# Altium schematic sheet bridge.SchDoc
size 431 x 279 mm; Date: Not shown in title block; ApprovedBy: Not shown in title block; CheckedBy: Not shown in title block; Author: Not shown in title block; CompanyName: Not shown in title block; Engineer: Not shown in title block; Organization: Not shown in title block; Address1: Not shown in title block; Address2: Not shown in title block; Address3: Not shown in title block; Address4: Not shown in title block; DocumentNumber: 3; Revision: Use project parameter SCH_Rev; SheetNumber: 3; SheetTotal: 6; PageSetup: Record=PageOptions¦CenterHorizontal=True¦CenterVertical=True¦PrintScale=1.00¦XCorrection=1.00¦YCorrection=1.00¦PrintKind=0¦BorderSize=5000000¦LeftOffset=0¦BottomOffset=0¦Orientation=2¦PaperLength=1000¦PaperWidth=1000¦Scale=100¦PaperSource=15¦PrintQuality=600¦MediaType=1¦DitherType=10¦PaperKind=Letter¦PrintScaleMode=1
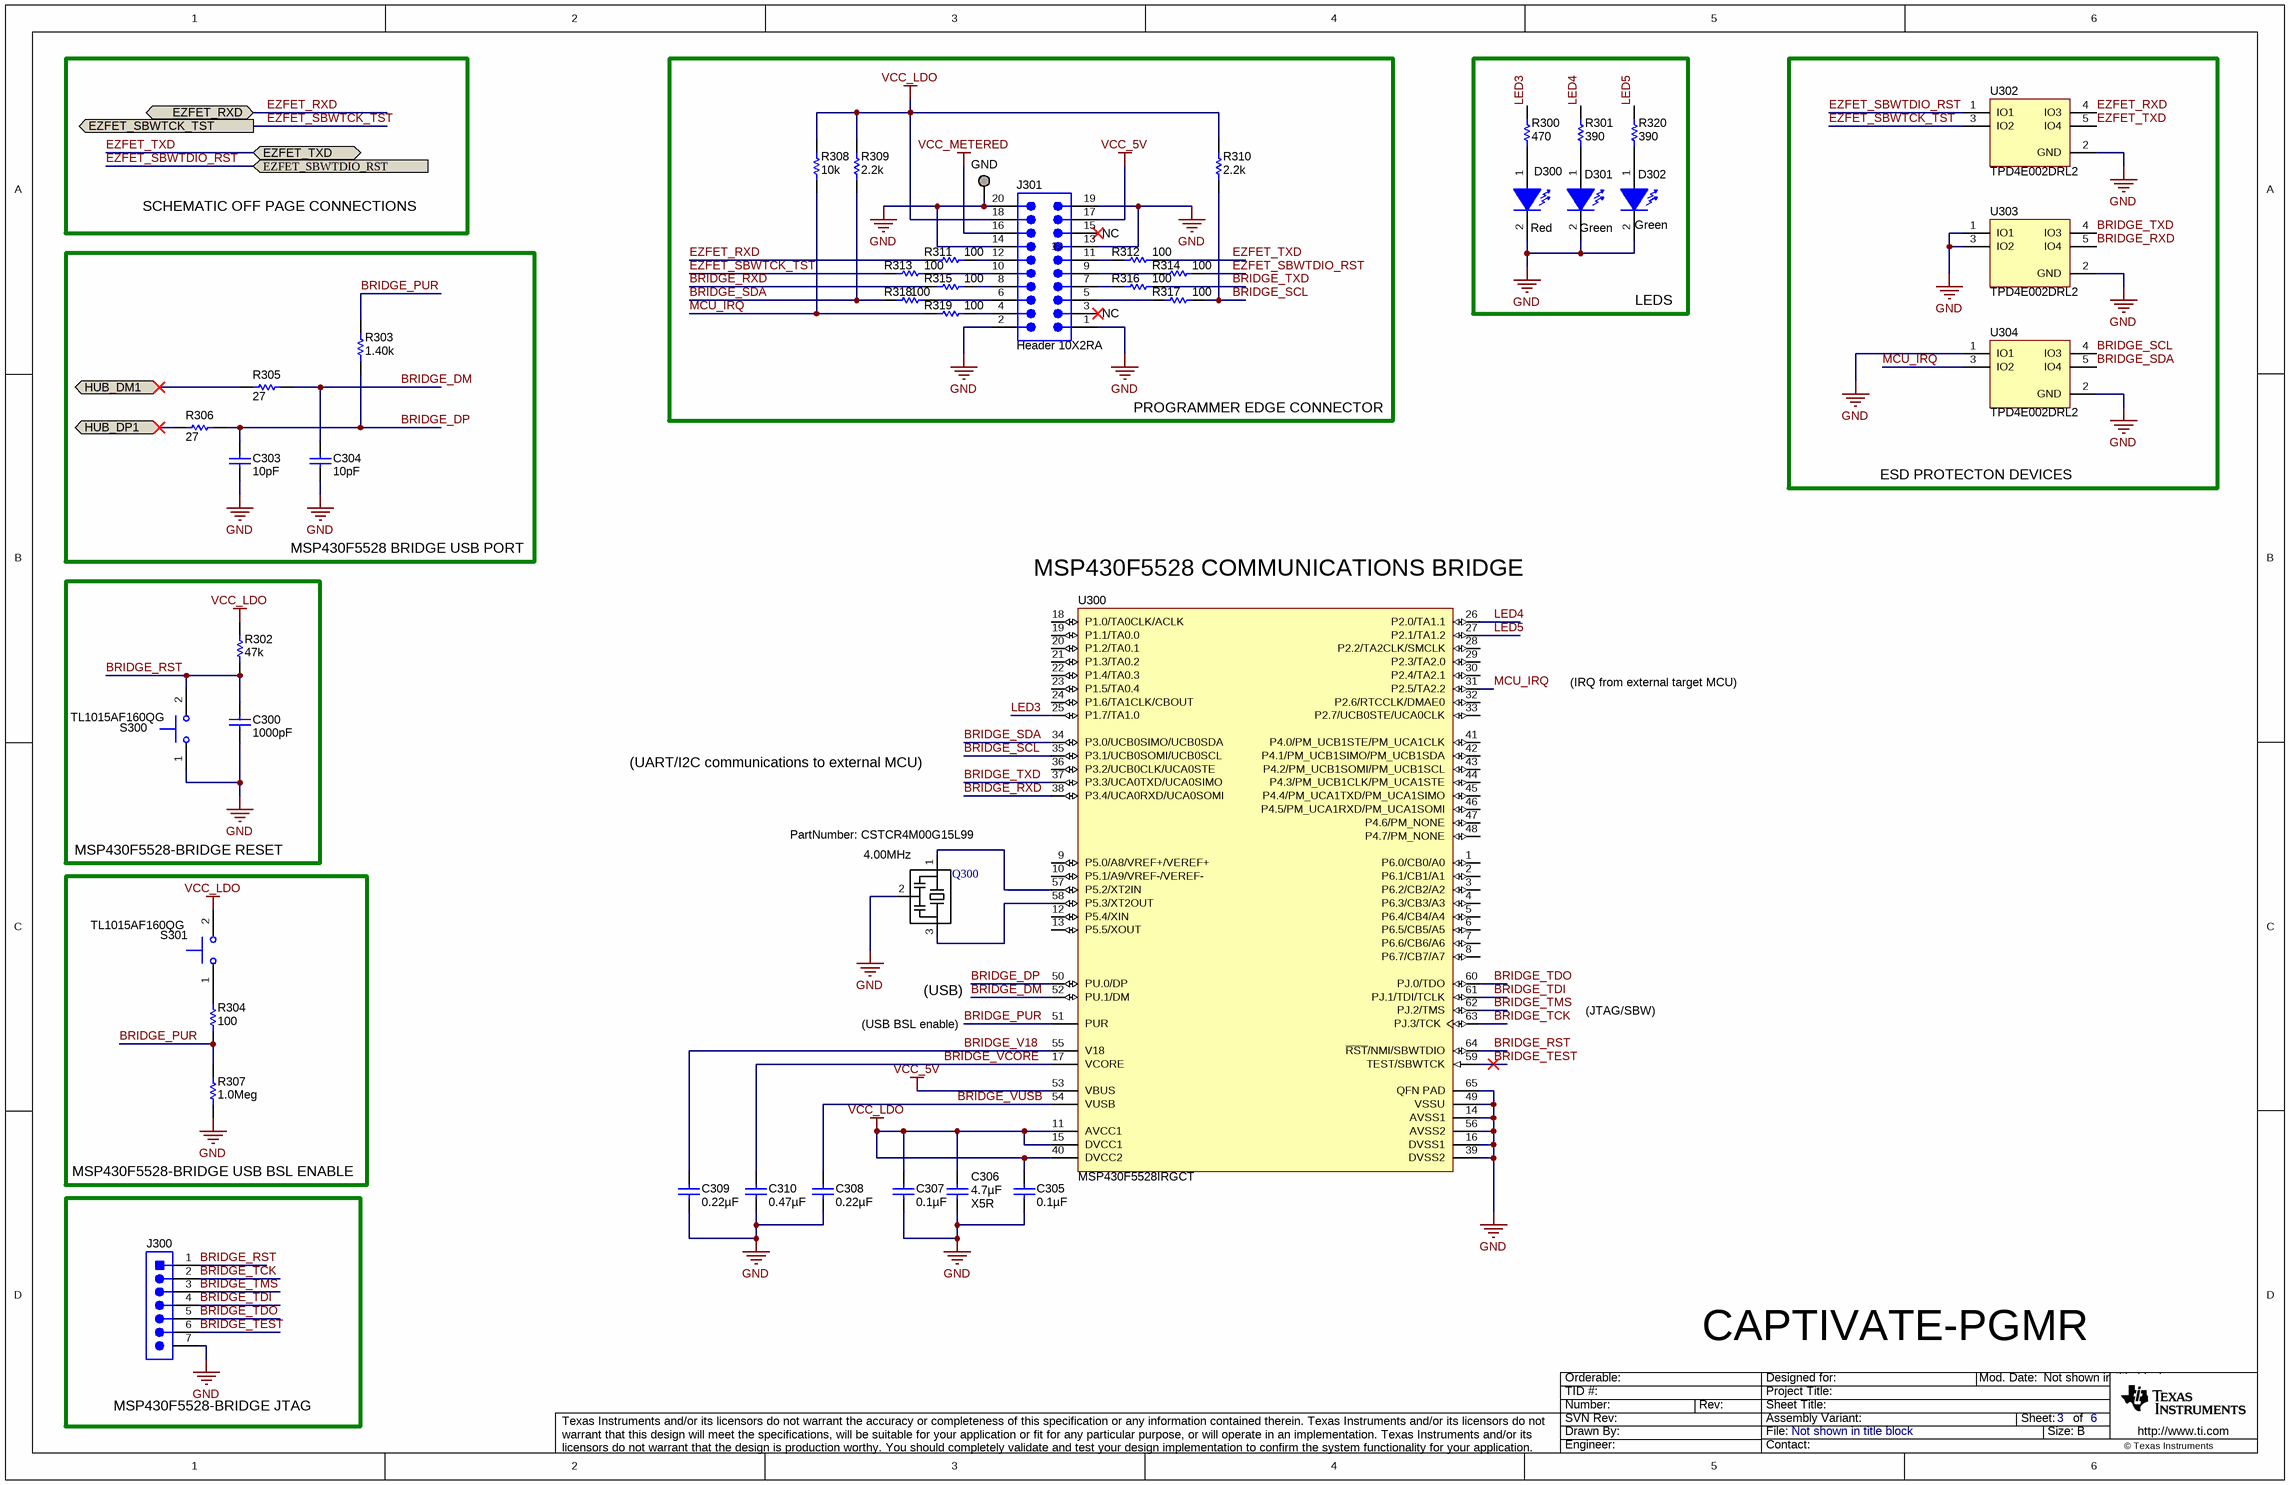
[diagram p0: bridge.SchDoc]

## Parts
C300  ValueDisplayed: 1000pF  [0402]  (hidden comment: C1005X7R1H102K)
C303  ValueDisplayed: 10pF  [0402]  (hidden comment: GRM1555C1H100JA01D)
C304  ValueDisplayed: 10pF  [0402]  (hidden comment: GRM1555C1H100JA01D)
C305  ValueDisplayed: 0.1µF  [0402]  (hidden comment: GRM155R61C104KA88D)
C306  ValueDisplayed: 4.7µF  TempCo: X5R  [0603]  (hidden comment: CGB3B1X5R1A475K055AC)
C307  ValueDisplayed: 0.1µF  [0402]  (hidden comment: GRM155R61C104KA88D)
C308  ValueDisplayed: 0.22µF  [0402]  (hidden comment: GRM155R61A224KE19D)
C309  ValueDisplayed: 0.22µF  [0402]  (hidden comment: GRM155R61A224KE19D)
C310  ValueDisplayed: 0.47µF  [0402]  (hidden comment: GRM155R61A474KE15D)
D300  value Red  [LED_LTST-C190_Red]  (hidden comment: LTST-C190CKT)
D301  value Green  [LED_LTST-C190]  (hidden comment: LTST-C190GKT)
D302  value Green  [LED_LTST-C190]  (hidden comment: LTST-C190GKT)
GND  TESTPOINT  [TP_VIA_060RND040]  (value not drawn)  (no BOM)
J300  GRPB071VWVN-RC  [Sullins_GRPB071VWVN-RC]  (value not drawn)
J301  Header 10X2RA  [HDR2X10RA]
Q300  Value Displayed: 4.00MHz  PartNumber: CSTCR4M00G15L99  [CSTCR CERAMIC RESONATOR - MURATA]  (hidden comment: RATA-FILTER_CSTCR4M00G15)
R300  value 470  [0402]  (hidden comment: CRCW0402470RJNED)
R301  value 390  [0402]  (hidden comment: CRCW0402390RJNED)
R302  value 47k  [0402]  (hidden comment: CRCW040247K0JNED)
R303  value 1.40k  [0402]  (hidden comment: CRCW04021K40FKED)
R304  value 100  [0402]  (hidden comment: CRCW0402100RJNED)
R305  value 27  [0402]  (hidden comment: CRCW040227R0JNED)
R306  value 27  [0402]  (hidden comment: CRCW040227R0JNED)
R307  value 1.0Meg  [0402]  (hidden comment: CRCW04021M00JNED)
R308  ValueDisplayed: 10k  [0402]  (hidden comment: CRCW040210K0JNED)
R309  ValueDisplayed: 2.2k  [0402]  (hidden comment: CRCW04022K20JNED)
R310  ValueDisplayed: 2.2k  [0402]  (hidden comment: CRCW04022K20JNED)
R311  ValueDisplayed: 100  [0402]  (hidden comment: CRCW0402100RJNED)
R312  ValueDisplayed: 100  [0402]  (hidden comment: CRCW0402100RJNED)
R313  ValueDisplayed: 100  [0402]  (hidden comment: CRCW0402100RJNED)
R314  ValueDisplayed: 100  [0402]  (hidden comment: CRCW0402100RJNED)
R315  ValueDisplayed: 100  [0402]  (hidden comment: CRCW0402100RJNED)
R316  ValueDisplayed: 100  [0402]  (hidden comment: CRCW0402100RJNED)
R317  ValueDisplayed: 100  [0402]  (hidden comment: CRCW0402100RJNED)
R318  ValueDisplayed: 100  [0402]  (hidden comment: CRCW0402100RJNED)
R319  ValueDisplayed: 100  [0402]  (hidden comment: CRCW0402100RJNED)
R320  value 390  [0402]  (hidden comment: CRCW0402390RJNED)
S300  TL1015AF160QG  [SW_TL1015AF160QG]
S301  TL1015AF160QG  [SW_TL1015AF160QG]
U300  MSP430F5528IRGCT  [RGC0064B]
U302  TPD4E002DRL2  [DRL0005A]
U303  TPD4E002DRL2  [DRL0005A]
U304  TPD4E002DRL2  [DRL0005A]

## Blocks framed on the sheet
PROGRAMMER EDGE CONNECTOR: GND J301 R308-R319
LEDS: D300-D302 R300 R301 R320
ESD PROTECTON DEVICES: U302-U304
MSP430F5528 BRIDGE USB PORT: C303 C304 R303 R305 R306
MSP430F5528-BRIDGE RESET: C300 R302 S300
MSP430F5528-BRIDGE USB BSL ENABLE: R304 R307 S301
MSP430F5528-BRIDGE JTAG: J300

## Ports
EZFET_RXD (bidir), EZFET_SBWTCK_TST, EZFET_SBWTDIO_RST, EZFET_TXD (bidir), HUB_DM1 (bidir), HUB_DP1 (bidir)

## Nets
GND: C300.2 C303.2 C304.2 C305.2 C306.2 C307.2 C308.2 C309.2 C310.2 D300.2(K) D301.2(K) D302.2(K) GND.1 J300.7 J301.1 J301.2 J301.13 J301.14 J301.19 J301.20 Q300.2 R307.1 S300.1 U300.14(AVSS1) U300.16(DVSS1) U300.39(DVSS2) U300.49(VSSU) U300.56(AVSS2) U300.65(QFN_PAD) U302.2(GND) U303.1(IO1) U303.2(GND) U303.3(IO2) U304.1(IO1) U304.2(GND)
VCC_5V: J301.17 U300.53(VBUS)
VCC_LDO: C305.1 C306.1 C307.1 J301.18 R302.2 R308.2 R309.2 R310.1 S301.2 U300.11(AVCC1) U300.15(DVCC1) U300.40(DVCC2)
VCC_METERED: J301.16
BRIDGE_DM: C304.1 R305.2 U300.52(PU.1/DM)
BRIDGE_DP: C303.1 R303.1 R306.2 U300.50(PU.0/DP)
BRIDGE_PUR: R303.2 R304.1 R307.2 U300.51(PUR)
BRIDGE_RST: C300.1 J300.1 R302.1 S300.2 U300.64(~{RST}/NMI/SBWTDIO)
BRIDGE_RXD: R315.1 U300.38(P3.4/UCA0RXD/UCA0SOMI) U303.5(IO4)
BRIDGE_SCL: R310.2 R317.2 U300.35(P3.1/UCB0SOMI/UCB0SCL) U304.4(IO3)
BRIDGE_SDA: R309.1 R318.1 U300.34(P3.0/UCB0SIMO/UCB0SDA) U304.5(IO4)
BRIDGE_TCK: J300.2 U300.63(PJ.3/TCK)
BRIDGE_TDI: J300.4 U300.61(PJ.1/TDI/TCLK)
BRIDGE_TDO: J300.5 U300.60(PJ.0/TDO)
BRIDGE_TEST: J300.6 U300.59(TEST/SBWTCK)
BRIDGE_TMS: J300.3 U300.62(PJ.2/TMS)
BRIDGE_TXD: R316.2 U300.37(P3.3/UCA0TXD/UCA0SIMO) U303.4(IO3)
BRIDGE_V18: C309.1 U300.55(V18)
BRIDGE_VCORE: C310.1 U300.17(VCORE)
BRIDGE_VUSB: C308.1 U300.54(VUSB)
EZFET_RXD: R311.1 U302.4(IO3) ; port EZFET_RXD
EZFET_SBWTCK_TST: R313.1 U302.3(IO2) ; port EZFET_SBWTCK_TST
EZFET_SBWTDIO_RST: R314.2 U302.1(IO1) ; port EZFET_SBWTDIO_RST
EZFET_TXD: R312.2 U302.5(IO4) ; port EZFET_TXD
HUB_DM1: R305.1 ; port HUB_DM1
HUB_DP1: R306.1 ; port HUB_DP1
LED3: R300.2 U300.25(P1.7/TA1.0)
LED4: R301.2 U300.26(P2.0/TA1.1)
LED5: R320.2 U300.27(P2.1/TA1.2)
MCU_IRQ: R308.1 R319.1 U300.31(P2.5/TA2.2) U304.3(IO2)
NetD300_1: D300.1(A) R300.1
NetD301_1: D301.1(A) R301.1
NetD302_1: D302.1(A) R320.1
NetJ301_4: J301.4 R319.2
NetJ301_5: J301.5 R317.1
NetJ301_6: J301.6 R318.2
NetJ301_7: J301.7 R316.1
NetJ301_8: J301.8 R315.2
NetJ301_9: J301.9 R314.1
NetJ301_10: J301.10 R313.2
NetJ301_11: J301.11 R312.1
NetJ301_12: J301.12 R311.2
NetQ300_1: Q300.1 U300.57(P5.2/XT2IN)
NetQ300_3: Q300.3 U300.58(P5.3/XT2OUT)
NetR304_2: R304.2 S301.1

Not connected (* = marked no-connect by the designer): J301 3* 15*; U300 1(P6.0/CB0/A0) 2(P6.1/CB1/A1) 3(P6.2/CB2/A2) 4(P6.3/CB3/A3) 5(P6.4/CB4/A4) 6(P6.5/CB5/A5) 7(P6.6/CB6/A6) 8(P6.7/CB7/A7) 9(P5.0/A8/VREF+/VEREF+) 10(P5.1/A9/VREF-/VEREF-) 12(P5.4/XIN) 13(P5.5/XOUT) 18(P1.0/TA0CLK/ACLK) 19(P1.1/TA0.0) 20(P1.2/TA0.1) 21(P1.3/TA0.2) 22(P1.4/TA0.3) 23(P1.5/TA0.4) 24(P1.6/TA1CLK/CBOUT) 28(P2.2/TA2CLK/SMCLK) 29(P2.3/TA2.0) 30(P2.4/TA2.1) 32(P2.6/RTCCLK/DMAE0) 33(P2.7/UCB0STE/UCA0CLK) 36(P3.2/UCB0CLK/UCA0STE) 41(P4.0/PM_UCB1STE/PM_UCA1CLK) 42(P4.1/PM_UCB1SIMO/PM_UCB1SDA) 43(P4.2/PM_UCB1SOMI/PM_UCB1SCL) 44(P4.3/PM_UCB1CLK/PM_UCA1STE) 45(P4.4/PM_UCA1TXD/PM_UCA1SIMO) 46(P4.5/PM_UCA1RXD/PM_UCA1SOMI) 47(P4.6/PM_NONE) 48(P4.7/PM_NONE)

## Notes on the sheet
- SCHEMATIC OFF PAGE CONNECTIONS
- NC
- (near U300) MSP430F5528 COMMUNICATIONS BRIDGE
- (IRQ from external target MCU)
- (UART/I2C communications to external MCU)
- (USB BSL enable)
- (USB)
- (JTAG/SBW)
- CAPTIVATE-PGMR

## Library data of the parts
C300 = C1005X7R1H102K: CAP, CERM, 1000pF, 50V, +/-10%, X7R, 0402; Manufacturer: TDK; Polarized: N; CompType: Capacitor; U/M: EA; Cap_F: 0.000000001; Tolerance_%: 10; ESR_Ohm: 0.2381; Value1: 0.2381 ohm; VDC_V: 50; TaMin_C: -55; TaMax_C: 125
C303 C304 = GRM1555C1H100JA01D: CAP, CERM, 10pF, 50V, +/-5%, C0G/NP0, 0402; Manufacturer: MuRata; Polarized: N; CompType: Capacitor; U/M: EA; Cap_F: 0.00000000001; Tolerance_%: 5; Value1: Unknown; VDC_V: 50; TaMin_C: -55; TaMax_C: 125
C305 C307 = GRM155R61C104KA88D: CAP, CERM, 0.1uF, 16V, +/-10%, X5R, 0402; Manufacturer: MuRata; Polarized: N; CompType: Capacitor; U/M: EA; Cap_F: 0.0000001; Tolerance_%: 10; Value1: Unknown; VDC_V: 16; TaMin_C: -55; TaMax_C: 85
C306 = CGB3B1X5R1A475K055AC: CAP, CERM, 4.7 µF, 10 V, +/- 10%, X5R, 0603; Manufacturer: TDK; Polarized: N; CompType: Capacitor; Value: 4.7uF; U/M: EA; Cap_F: 0.0000047; Tolerance_%: 10; Value1: Unknown; VDC_V: 10V; TaMin_C: -55; TaMax_C: 85
C308 C309 = GRM155R61A224KE19D: CAP, CERM, 0.22uF, 10V, +/-10%, X5R, 0402; Manufacturer: MuRata; Polarized: N; CompType: Capacitor; U/M: EA; Cap_F: 0.00000022; Tolerance_%: 10; Value1: Unknown; TaMin_C: -55; TaMax_C: 85
C310 = GRM155R61A474KE15D: CAP, CERM, 0.47uF, 10V, +/-10%, X5R, 0402; Manufacturer: MuRata; Polarized: N; CompType: Capacitor; U/M: EA; Cap_F: 0.00000047; Tolerance_%: 10; Value1: Unknown; TaMin_C: -55; TaMax_C: 85
D300 = LTST-C190CKT: LED, Red, SMD; Manufacturer: Lite-On; Vf_V: 2; Value2: 2V; Io_A: 0.02; Tjmax_C: 85; Power_TotalModule: 0.0625; Value1: 0.0625W; U/M: EA
D301 D302 = LTST-C190GKT: LED, Green, SMD; Manufacturer: Lite-On; Vf_V: 2.1; Value2: 2.1V; Io_A: 0.02; Power_TotalModule: 0.1; Value1: 0.1W; U/M: EA
GND = TESTPOINT: TEST POINT.  No entry in BOM.
J300 = GRPB071VWVN-RC: Header, 50mil, 7x1, Gold,  TH; Manufacturer: Sullins Connector Solutions; U/M: EA
J301 = Header 10X2RA: Header, Male, 10-Pin, 2 row, Shround, Right Angle; Manufacturer: Samtec; PartNumber: TSSH-110-01-L-D-RA
Q300 = MURATA-FILTER_CSTCR4M00G15: 4.00MHz resonator
R300 = CRCW0402470RJNED: RES, 470 ohm, 5%, 0.063W, 0402; Manufacturer: Vishay-Dale; CompType: Resistor; Value_Code: 470R; Tolerance_%: 5; Power_W: 0.063; VDC_V: 50; TempCo: 200 ppm/C; EIA_Code: E24; U/M: EA
R301 R320 = CRCW0402390RJNED: RES, 390 ohm, 5%, 0.063W, 0402; Manufacturer: Vishay-Dale; CompType: Resistor; Value_Code: 390R; Tolerance_%: 5; Power_W: 0.063; VDC_V: 50; TempCo: 200 ppm/C; EIA_Code: E24; U/M: EA
R302 = CRCW040247K0JNED: RES, 47k ohm, 5%, 0.063W, 0402; Manufacturer: Vishay-Dale; CompType: Resistor; Res_ohm: 47000; Value_Code: 47k0; Tolerance_%: 5; Power_W: 0.063; VDC_V: 50; TempCo: 200 ppm/C; EIA_Code: E24; U/M: EA
R303 = CRCW04021K40FKED: RES, 1.40k ohm, 1%, 0.063W, 0402; Manufacturer: Vishay-Dale; CompType: Resistor; Res_ohm: 1400; Value_Code: 1k40; Tolerance_%: 1; Power_W: 0.063; VDC_V: 50; TempCo: 100 ppm/C; EIA_Code: E96; U/M: EA
R304 = CRCW0402100RJNED: RES, 100 ohm, 5%, 0.063W, 0402; Manufacturer: Vishay-Dale; CompType: Resistor; Value_Code: 100R; Tolerance_%: 5; Power_W: 0.063; VDC_V: 50; TempCo: 200 ppm/C; EIA_Code: E24; U/M: EA
R305 R306 = CRCW040227R0JNED: RES, 27 ohm, 5%, 0.063W, 0402; Manufacturer: Vishay-Dale; CompType: Resistor; Value_Code: 27R0; Tolerance_%: 5; Power_W: 0.063; VDC_V: 50; TempCo: 200 ppm/C; EIA_Code: E24; U/M: EA
R307 = CRCW04021M00JNED: RES, 1.0Meg ohm, 5%, 0.063W, 0402; Manufacturer: Vishay-Dale; CompType: Resistor; Res_ohm: 1000000; Value_Code: 1M00; Tolerance_%: 5; Power_W: 0.063; VDC_V: 50; TempCo: 200 ppm/C; EIA_Code: E24; U/M: EA
R308 = CRCW040210K0JNED: RES, 10 k, 5%, 0.063 W, 0402; Manufacturer: Vishay-Dale; CompType: Resistor; Value: 10k; Res_ohm: 10000; Value_Code: 10k0; Tolerance_%: 5; Power_W: 0.063; Value2: 0.063W; VDC_V: 50; TempCo: 200 ppm/C; EIA_Code: E24; U/M: EA
R309 R310 = CRCW04022K20JNED: RES, 2.2 k, 5%, 0.063 W, 0402; Manufacturer: Vishay-Dale; CompType: Resistor; Value: 2.2k; Res_ohm: 2200; Value_Code: 2k20; Tolerance_%: 5; Power_W: 0.063; Value2: 0.063W; VDC_V: 50; TempCo: 200 ppm/C; EIA_Code: E24; U/M: EA
R311-R319 = CRCW0402100RJNED: RES, 100, 5%, 0.063 W, 0402; Manufacturer: Vishay-Dale; CompType: Resistor; Value: 100; Value_Code: 100R; Tolerance_%: 5; Power_W: 0.063; Value2: 0.063W; VDC_V: 50; TempCo: 200 ppm/C; EIA_Code: E24; U/M: EA
S300 S301 = TL1015AF160QG: Switch, Tactile, SPST-NO, 0.05A, 12V, SMT; Manufacturer: E-Switch; SymbolCreator: a0412235; VDC_V: 12; SwitchFunction: Off-Mom; PositionCount: 1; CurrentRating_mA: 50
U300 = MSP430F5528IRGCT: 25 MHz Mixed Signal Microcontroller with 128 KB Flash, 8192 B SRAM and 47 GPIOs, -40 to 85 degC, 64-pin QFN (RGC), Green (RoHS & no Sb/Br); Manufacturer: Texas Instruments; ADC: 12-bit SAR; ADC Channels: 16; Brown Out Reset: Yes; DMA: 3; Flash(KB): 128; Frequency(MHz): 25; GPIO: 47; Multiplier: 32x32; SRAM(B): 8192; SubFamily: 5 Series; Timers - 16-bit: 4; USB: 1; USCI_A (UART/LIN/IrDA/SPI): 2
U302-U304 = TPD4E002DRL2: Low-Capacitance Array with + / - 15 kV ESD Protection, 4 Channels, -40 to +85 degC, 5-pin SOT (DRL), Green (RoHS & no Sb/Br); Manufacturer: Texas Instruments; Alternate Manufacturer: None; Alternate PartNumber: Equivalent; Breakdown Voltage(Min)(V): 6; IEC 61000-4-2 Air-Gap(+/- kV): 15; IO Capacitance(Typ)(pF): 11; IO Leakage Current(nA): 100; SubFamily: ESD Solution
